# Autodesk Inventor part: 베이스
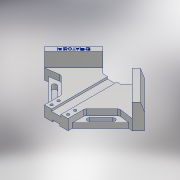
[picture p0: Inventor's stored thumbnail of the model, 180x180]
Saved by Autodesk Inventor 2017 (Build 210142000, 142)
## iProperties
Part Number: 베이스
Material: 알루미늄 6061
Document SubType Name: Modeling
Designer: 00-00
Mass: 571.445 g
Surface Area: 406.807 cm^2
Volume: 211.646 cm^3
Density: 2.7 g/cm^3
Appearance: 알루미늄 - 평지
Author: 00-00
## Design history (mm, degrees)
sketch "스케치1"
  geometry: L1 (-84.853, 0)-(0, -84.853); L2 (0, -84.853)-(84.853, 0); L3 (84.853, 0)-(0, 84.853); L4 (0, 84.853)-(-84.853, 0); 1 further point
  constraints: 8 end point, 2 horizontal alignment, 2 parallel, 2 vertical alignment, 1 perpendicular
  dimensions: "d0" = 120 distance of L3.end L1.start
extrude "돌출1" new body sketch "스케치1" distance "d1" = 18; taper "d2" = 0 deg
sketch "스케치2"
  geometry: L1 (-84.853, 0)-(0, -84.853) reference; L2 (84.853, 0)-(0, 84.853) reference; L3 (0, 84.853)-(-84.853, 0) reference; L4 (0, -84.853)-(-20, -84.853); L5 (-20, -84.853)-(-20, -64.853); L6 (-20, -64.853)-(0, -64.853); L7 (0, -64.853)-(0, -84.853); L8 (0, -64.853)-(0, 30.147); L9 (-16.005, 30.147)-(16.005, 30.147); L10 (16.005, 30.147)-(35.355, 49.497); L11 (-16.005, 30.147)-(-35.355, 49.497); 1 further point
  constraints: 16 end point, 3 perpendicular, 3 point on line, 2 horizontal, 2 parallel, 1 midpoint, 1 vertical
  dimensions: "d3" = 20 distance of L4.end L5.end; "d4" = 95 distance of L6.end L8.end; "d5" = 50 distance from line of L11 L2.end; "d6" = 50 distance from line of L10 L2.end
extrude "돌출2" cut sketch "스케치2" distance "d7" = 100; taper "d8" = 0 deg
extrude "돌출3" cut sketch "스케치2" distance "d9" = 100; taper "d10" = 0 deg
sketch "스케치3"
  geometry: L1 (-35.355, 49.497)-(-84.853, 0) reference; L2 (-84.853, 0)-(-20, -64.853) reference; L3 (-35.355, 49.497)-(-16.005, 30.147) reference; L4 (-24.749, 38.891)-(-74.246, -10.607); L5 (-74.246, -10.607)-(-49.497, -7.071); L6 (-49.497, -7.071)-(-20, -36.569); L7 (-29.698, -38.184)-(-49.497, -18.385); L8 (-32.527, -41.012)-(-52.326, -21.213); L9 (-46.669, -15.556)-(-26.87, -35.355); L10 (-20, -64.853)-(-20, -36.569); L11 (-68.059, -9.723)-(-20, -57.782); A1 r 4 centre (-29.698, -38.184) between (-32.527, -41.012) and (-26.87, -35.355); A2 r 4 centre (-49.497, -18.385) between (-46.669, -15.556) and (-52.326, -21.213); 2 further points
  constraints: 18 end point, 4 point on circle, 4 point on line, 4 tangent, 3 parallel, 2 centre point, 1 midpoint, 1 perpendicular, 1 vertical
  dimensions: "d11" = 15 distance between parallel lines of L1 L4; "d12" = 30 distance from line of L1 L5.end; "d13" = 20 distance between parallel lines of L6 L2; "d15" = 5 distance between parallel lines of L11 L2; "d16" = 12 distance from line of point (-39.598, -28.284) L2; "d17" = 8 distance between parallel lines of L9 L8; "d18" = 38 distance from line of L7.end L1; "d19" = 28 distance of L7.start L7.end
extrude "돌출4" join sketch "스케치3" distance "d20" = 24; taper "d21" = 0 deg
extrude "돌출5" cut sketch "스케치3" distance "d22" = 24; taper "d23" = 0 deg
extrude "돌출6" cut sketch "스케치3" distance "d24" = 10; taper "d25" = 0 deg
extrude "돌출7" cut sketch "스케치3" distance "d26" = 100; taper "d27" = 0 deg
sketch "스케치4"
  geometry: L1 (-20, -64.853)-(20, -64.853) reference; L2 (-14, -46.853)-(14, -46.853); L3 (14, -46.853)-(14, -58.853); L4 (14, -58.853)-(-14, -58.853); L5 (-14, -58.853)-(-14, -46.853); 7 further points
  constraints: 8 end point, 4 coincident, 2 midpoint, 2 parallel, 1 horizontal, 1 perpendicular, 1 vertical alignment
  dimensions: "d28" = 6 distance between parallel lines of L4 L1; "d29" = 12 distance between parallel lines of L2 L4; "d54" = 28 distance of L3.end L4.end
sketch "스케치5"
  geometry: L1 (40, 0)-(0, 0) reference; L2 (0, 18)-(40, 18) reference; L3 (12, 18)-(28, 18); L4 (28, 18)-(28, 14.5); L5 (28, 14.5)-(12, 14.5); L6 (12, 14.5)-(12, 18); L7 (14, 0)-(26, 0); L8 (26, 0)-(26, 3); L9 (26, 3)-(14, 3); L10 (14, 3)-(14, 0); 5 further points
  constraints: 16 end point, 4 midpoint, 4 parallel, 2 coincident, 2 horizontal, 2 perpendicular, 2 point on line
  dimensions: "d44" = 3.5 distance of L3.end L4.end; "d45" = 3 distance of L7.end L8.end; "d46" = 12 distance of L8.end L9.end; "d47" = 16 distance of L4.end L5.end
extrude "돌출8" cut sketch "스케치5" distance "d48" = 200; taper "d49" = 0 deg
sketch "스케치6"
  geometry: L1 (15, 0)-(0, 0) reference; L2 (5, 0)-(0, 15); L3 (0, 42)-(0, 0) reference; L4 (5, 0)-(0, 0); L5 (0, 15)-(0, 0); 1 further point
  constraints: 6 end point, 2 point on line, 1 collinear, 1 perpendicular
  dimensions: "d50" = 5 distance of L2.start L1.end; "d51" = 15 distance of L1.end L2.end
extrude "돌출9" cut sketch "스케치6" distance "d52" = 200; taper "d53" = 0 deg
hole "구멍3" sketch "스케치4" diameter "d55" = 8; stored, may be unused: countersink angle "d59" = 90 deg, drill point angle "d61" = 0 deg; dims "d56" = 6, "d57" = 4, "d58" = 2, "d60" = 10
hole "구멍4" sketch "스케치4" diameter "d62" = 4.5; stored, may be unused: countersink angle "d66" = 90 deg, drill point angle "d68" = 118 deg; dims "d63" = 6, "d64" = 4, "d65" = 2, "d67" = 10
sketch "스케치7"
  geometry: L1 (-74.246, -10.607)-(-24.749, 38.891) reference; L2 (-24.749, 38.891)-(-31.82, 45.962) reference; 2 further points
  constraints: 1 other
  dimensions: "d69" = 5 distance from line of L1 point (-53.033, 17.678); "d70" = 35 distance from line of L2 point (-53.033, 17.678)
feature "엠보싱1" sketch "스케치7" dims "d0" = 120, "d71" = 0.5, "d72" = 0
fillet "모깎기1" dims "d73" = 5
node "솔리드1"
mirror "미러1"
mirror "미러2"
mirror "미러3"
